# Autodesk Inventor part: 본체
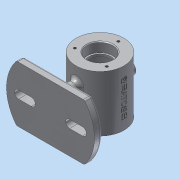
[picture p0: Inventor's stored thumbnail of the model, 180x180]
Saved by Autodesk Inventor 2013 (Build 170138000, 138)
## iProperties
Created: 2017-12
Part Number: 본체
Material: 알루미늄 6061
Document SubType Name: Modeling
Designer: Administrator
Density: 1 g/cm^3
Author: Administrator
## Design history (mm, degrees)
sketch "스케치1"
  geometry: C1 r 30 at (0, 0); 1 further point
  constraints: 1 centre point, 1 coincident
  dimensions: "d2" = 30 radius of C1
extrude "돌출1" new body sketch "스케치1" stored distance "d3" = 70; taper "d4" = 0 deg
sketch "스케치2"
  geometry: C1 r 30 at (0, 0) reference; 1 further point
  constraints: 1 vertical alignment
  dimensions: "d5" = 23 distance of C1.centre point (0, 23)
hole "구멍1" sketch "스케치2" at (0, 23) diameter "d6" = 3.242; stored, may be unused: countersink angle "d10" = 90 deg, drill point angle "d12" = 118 deg; dims "d7" = 8, "d8" = 4, "d9" = 2, "d11" = 10
node "작업 평면1"
sketch "스케치3"
  geometry: C1 r 8 at (0, 0); 1 further point
  constraints: 1 centre point, 1 coincident
  dimensions: "d17" = 8 radius of C1
extrude "돌출2" join sketch "스케치3" stored distance "d18" = 70; taper "d19" = 0 deg
hole "구멍2" diameter "d22" = 28; stored, may be unused: countersink angle "d26" = 90 deg, drill point angle "d28" = 0 deg; dims "d23" = 28, "d24" = 32, "d25" = 12, "d27" = 15, "d29" = 10, "d30" = 10
hole "구멍3" diameter "d33" = 50; stored, may be unused: countersink angle "d37" = 90 deg, drill point angle "d39" = 0 deg; dims "d31" = 10, "d32" = 10, "d34" = 28, "d35" = 32, "d36" = 12, "d38" = 40
hole "구멍4" diameter "d42" = 8; stored, may be unused: countersink angle "d46" = 90 deg, drill point angle "d48" = 0 deg; dims "d40" = 10, "d41" = 10, "d43" = 28, "d44" = 32, "d45" = 12, "d47" = 40
node "작업 평면2"
sketch "스케치4"
  geometry: L1 (42.426, 35)-(-42.426, 35); L2 (42.426, -35)-(-42.426, -35); L3 (0, 35)-(0, -35); L4 (40, 5)-(24, 5); L5 (24, 5)-(32, 5); L6 (24, -5)-(40, -5); A1 r 55 centre (0, 0) between (42.426, -35) and (42.426, 35); A2 r 55 centre (0, 0) between (-42.426, 35) and (-42.426, -35); A3 r 5 centre (24, 0) between (24, 5) and (24, -5); A4 r 5 centre (40, 0) between (40, -5) and (40, 5); 2 further points
  constraints: 12 end point, 8 point on circle, 4 centre point, 4 midpoint, 4 tangent, 2 parallel, 1 coincident, 1 horizontal, 1 horizontal alignment, 1 perpendicular
  dimensions: "d51" = 70 distance between parallel lines of L2 L1; "d52" = 35 distance from line of point (0, 0) L1 (= 0.5 x d51); "d53" = 55 radius of A1; "d54" = 55 radius of A2; "d56" = 5 radius of A4; "d57" = 16 distance of A3.centre A4.centre; "d58" = 24 distance of point (0, 0) A3.centre
extrude "돌출3" join sketch "스케치4" distance "d59" = 10; taper "d60" = 0 deg
sketch "스케치5"
  geometry: L1 (42.426, 35)-(-42.426, 35) reference; L2 (-5, 15)-(-5, -15); L3 (5, -15)-(5, 15); L4 (-42.426, -35)-(42.426, -35) reference; L5 (24, 5)-(40, 5); L6 (40, -5)-(24, -5); A1 r 55 centre (0, 0) between (42.426, -35) and (42.426, 35) reference; A2 r 5 centre (0, -15) between (-5, -15) and (5, -15); A3 r 5 centre (0, 15) between (5, 15) and (-5, 15); A4 r 5 centre (40, 0) between (40, -5) and (40, 5); A5 r 5 centre (24, 0) between (24, 5) and (24, -5)
  constraints: 8 end point, 8 point on circle, 8 tangent, 4 centre point, 3 parallel, 1 horizontal alignment, 1 perpendicular, 1 vertical alignment
  dimensions: "d61" = 5 radius of A3; "d63" = 30 distance of A2.centre A3.centre; "d64" = 15 distance of A1.centre A3.centre (= 0.5 x d63); "d67" = 5 radius of A5; "d68" = 16 distance of A4.centre A5.centre; "d69" = 24 distance of A5.centre A1.centre
extrude "돌출4" join sketch "스케치5" stored distance "d65" = 10; taper "d66" = 0 deg
extrude "돌출5" cut sketch "스케치5" distance "d70" = 10; taper "d71" = 0 deg
node "작업 평면3"
sketch "스케치6"
  geometry: L1 (30, -35)-(30, 35) reference; 2 further points
  constraints: 1 coincident, 1 other
  dimensions: "d72" = 30 distance from line of point (0, 0) L1
feature "엠보싱1" sketch "스케치6" dims "d3" = 70, "d4" = 0, "d73" = 0.5, "d74" = 0
chamfer "모따기1" distance "d75" = 1; stored, may be unused: second distance "d76" = 2, angle "d77" = 45 deg
fillet "모깎기1" dims "d78" = 0.3
fillet "모깎기2" dims "d79" = 3
fillet "모깎기3" dims "d80" = 5
node "솔리드1"
pattern_circular "원형 패턴1" dims angle "d14" = 360 deg
mirror "대칭1"
mirror "대칭2"
other parameters: "d16" = 37, "d49" = -62, "d50" = 55
